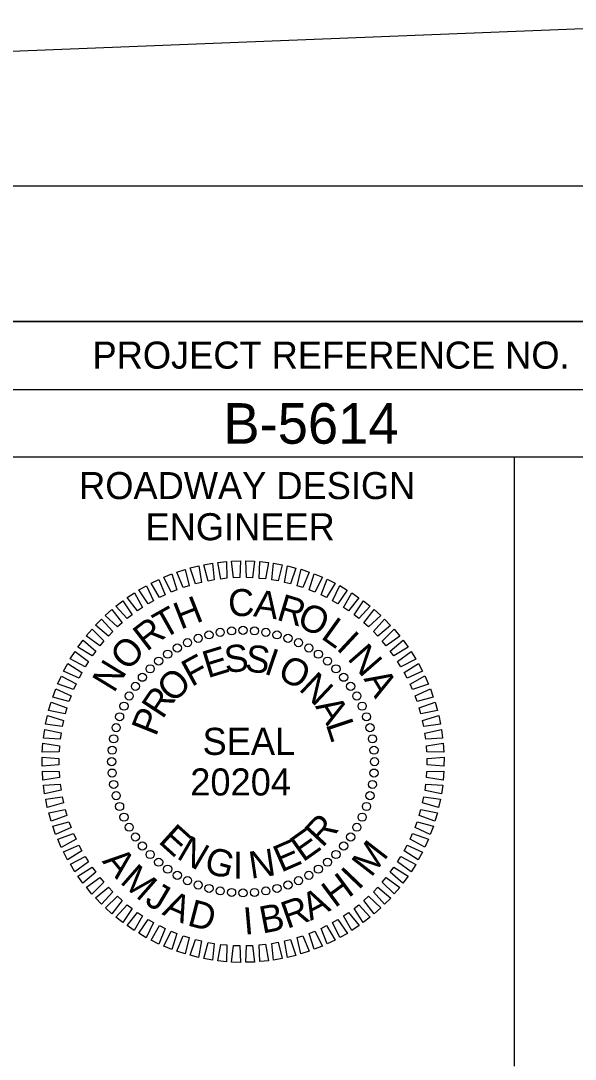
# Model space of a CAD drawing. Extents: x 1637092 to 1638792, y 884647 to 885778.
# Drawn here: x 1638575.6 to 1638677.9, y 885585.9 to 885777.7 of the extents above; entities that cross this region are included whole.
import ezdxf

# ---------------------------------------------------------------- set-up
doc = ezdxf.new("R2010")
doc.units = 0
for name, color, linetype in [('Scratch_Level_3', 7, 'Continuous'), ('Sheet Cutting Line CELL', 7, 'Continuous'), ('Sheet Data Field CELL', 7, 'Continuous'), ('Sheet PE Seal Cell', 7, 'Continuous'), ('Sheet Plan And Profile CELL', 7, 'Continuous'), ('Sheet Profile CELL', 7, 'Continuous'), ('Stewart Plot Border Xerox6279 and LJ5000', 7, 'Continuous')]:
    doc.layers.add(name, color=color, linetype=linetype)

msp = doc.modelspace()

# ---------------------------------------------------------------- linework, layer by layer
at = {"layer": 'Scratch_Level_3'}
msp.add_lwpolyline([(1637316.66, 885722.14), (1637316.66, 884697.14), (1638716.66, 884697.14), (1638716.66, 885777.71)], close=True, dxfattribs=at)
at = {"layer": 'Sheet Cutting Line CELL'}
msp.add_line((1638783.66, 885747.14), (1637099.66, 885747.14), dxfattribs=at)
at = {"layer": 'Sheet PE Seal Cell'}
msp.add_line((1638616.59, 885640.84), (1638616.59, 885640.84), dxfattribs=at)
for points in [[(1638607.82, 885673.68), (1638606.84, 885676.64), (1638608.41, 885677), (1638608.92, 885673.96)], [(1638610.13, 885674.21), (1638609.36, 885677.23), (1638610.95, 885677.49), (1638611.25, 885674.42)], [(1638612.47, 885674.58), (1638611.91, 885677.65), (1638613.52, 885677.79), (1638613.61, 885674.71)], [(1638614.84, 885674.79), (1638614.49, 885677.89), (1638616.11, 885677.91), (1638615.98, 885674.83)], [(1638617.21, 885674.83), (1638617.08, 885677.94), (1638618.7, 885677.86), (1638618.35, 885674.79)], [(1638619.58, 885674.7), (1638619.67, 885677.82), (1638621.27, 885677.62), (1638620.72, 885674.59)], [(1638621.93, 885674.41), (1638622.24, 885677.51), (1638623.83, 885677.21), (1638623.06, 885674.22)], [(1638624.26, 885673.95), (1638624.79, 885677.03), (1638626.35, 885676.61), (1638625.37, 885673.69)], [(1638603.33, 885672.14), (1638601.95, 885674.93), (1638603.46, 885675.51), (1638604.39, 885672.57)], [(1638605.55, 885672.99), (1638604.36, 885675.87), (1638605.91, 885676.34), (1638606.63, 885673.35)], [(1638626.55, 885673.34), (1638627.29, 885676.37), (1638628.82, 885675.84), (1638627.64, 885672.99)], [(1638628.8, 885672.57), (1638629.74, 885675.54), (1638631.23, 885674.91), (1638629.86, 885672.14)], [(1638599.11, 885669.99), (1638597.35, 885672.56), (1638598.76, 885673.35), (1638600.09, 885670.57)], [(1638601.18, 885671.14), (1638599.61, 885673.83), (1638601.07, 885674.51), (1638602.21, 885671.64)], [(1638630.98, 885671.64), (1638632.13, 885674.54), (1638633.57, 885673.8), (1638632.01, 885671.14)], [(1638633.09, 885670.56), (1638634.44, 885673.37), (1638635.83, 885672.54), (1638634.09, 885669.99)], [(1638597.12, 885668.7), (1638595.18, 885671.14), (1638596.54, 885672.02), (1638598.06, 885669.34)], [(1638635.13, 885669.33), (1638636.67, 885672.05), (1638637.99, 885671.12), (1638636.08, 885668.7)], [(1638593.43, 885665.72), (1638591.17, 885667.87), (1638592.39, 885668.93), (1638594.27, 885666.49)], [(1638595.22, 885667.27), (1638593.12, 885669.58), (1638594.41, 885670.55), (1638596.12, 885667.98)], [(1638637.07, 885667.97), (1638638.8, 885670.57), (1638640.05, 885669.55), (1638637.97, 885667.28)], [(1638638.91, 885666.48), (1638640.82, 885668.95), (1638642, 885667.85), (1638639.76, 885665.72)], [(1638591.75, 885664.04), (1638589.35, 885666.03), (1638590.49, 885667.17), (1638592.54, 885664.87)], [(1638640.64, 885664.86), (1638642.72, 885667.19), (1638643.82, 885666.01), (1638641.44, 885664.04)], [(1638590.19, 885662.25), (1638587.66, 885664.07), (1638588.72, 885665.29), (1638590.92, 885663.13)], [(1638642.26, 885663.12), (1638644.49, 885665.3), (1638645.51, 885664.05), (1638643, 885662.25)], [(1638588.76, 885660.36), (1638586.11, 885661.99), (1638587.08, 885663.28), (1638589.43, 885661.28)], [(1638643.75, 885661.28), (1638646.13, 885663.3), (1638647.06, 885661.97), (1638644.43, 885660.36)], [(1638587.47, 885658.37), (1638584.71, 885659.82), (1638585.59, 885661.17), (1638588.07, 885659.34)], [(1638645.11, 885659.33), (1638647.63, 885661.18), (1638648.46, 885659.8), (1638645.72, 885658.37)], [(1638586.32, 885656.29), (1638583.46, 885657.54), (1638584.24, 885658.96), (1638586.85, 885657.3)], [(1638646.33, 885657.3), (1638648.97, 885658.97), (1638649.7, 885657.53), (1638646.88, 885656.29)], [(1638585.31, 885654.14), (1638582.37, 885655.19), (1638583.06, 885656.66), (1638585.77, 885655.19)], [(1638647.41, 885655.18), (1638650.16, 885656.67), (1638650.79, 885655.18), (1638647.88, 885654.14)], [(1638584.46, 885651.93), (1638581.46, 885652.77), (1638582.04, 885654.28), (1638584.85, 885653)], [(1638648.33, 885653), (1638651.18, 885654.29), (1638651.7, 885652.76), (1638648.73, 885651.93)], [(1638583.77, 885649.66), (1638580.71, 885650.29), (1638581.18, 885651.84), (1638584.07, 885650.76)], [(1638649.11, 885650.76), (1638652.03, 885651.84), (1638652.45, 885650.28), (1638649.43, 885649.66)], [(1638583.23, 885647.35), (1638580.14, 885647.76), (1638580.5, 885649.34), (1638583.46, 885648.47)], [(1638649.72, 885648.46), (1638652.71, 885649.34), (1638653.02, 885647.76), (1638649.96, 885647.35)], [(1638582.86, 885645.01), (1638579.74, 885645.2), (1638580, 885646.8), (1638583.01, 885646.14)], [(1638650.17, 885646.13), (1638653.22, 885646.8), (1638653.41, 885645.2), (1638650.34, 885645)], [(1638582.65, 885642.64), (1638579.53, 885642.62), (1638579.67, 885644.23), (1638582.72, 885643.78)], [(1638650.46, 885643.78), (1638653.54, 885644.23), (1638653.63, 885642.62), (1638650.54, 885642.64)], [(1638582.61, 885640.27), (1638579.5, 885640.03), (1638579.52, 885641.65), (1638582.6, 885641.41)], [(1638650.58, 885641.41), (1638653.69, 885641.65), (1638653.66, 885640.03), (1638650.59, 885640.27)], [(1638582.73, 885637.9), (1638579.64, 885637.45), (1638579.56, 885639.06), (1638582.64, 885639.04)], [(1638650.54, 885639.04), (1638653.66, 885639.06), (1638653.52, 885637.45), (1638650.46, 885637.9)], [(1638583.02, 885635.55), (1638579.97, 885634.88), (1638579.77, 885636.48), (1638582.85, 885636.68)], [(1638650.33, 885636.67), (1638653.44, 885636.48), (1638653.19, 885634.88), (1638650.18, 885635.54)], [(1638583.47, 885633.22), (1638580.47, 885632.34), (1638580.17, 885633.92), (1638583.22, 885634.33)], [(1638649.96, 885634.33), (1638653.05, 885633.92), (1638652.68, 885632.34), (1638649.72, 885633.21)], [(1638584.08, 885630.92), (1638581.16, 885629.84), (1638580.74, 885631.4), (1638583.76, 885632.02)], [(1638649.42, 885632.02), (1638652.48, 885631.39), (1638652, 885629.85), (1638649.11, 885630.92)], [(1638584.85, 885628.68), (1638582.01, 885627.39), (1638581.48, 885628.92), (1638584.45, 885629.75)], [(1638648.72, 885629.75), (1638651.73, 885628.91), (1638651.15, 885627.4), (1638648.34, 885628.68)], [(1638585.78, 885626.5), (1638583.03, 885625.01), (1638582.4, 885626.5), (1638585.31, 885627.54)], [(1638647.87, 885627.54), (1638650.81, 885626.49), (1638650.13, 885625.02), (1638647.41, 885626.49)], [(1638586.85, 885624.38), (1638584.22, 885622.71), (1638583.48, 885624.15), (1638586.31, 885625.39)], [(1638646.87, 885625.39), (1638649.73, 885624.14), (1638648.94, 885622.72), (1638646.34, 885624.38)], [(1638588.07, 885622.35), (1638585.56, 885620.5), (1638584.73, 885621.88), (1638587.46, 885623.31)], [(1638645.72, 885623.31), (1638648.48, 885621.87), (1638647.6, 885620.51), (1638645.12, 885622.34)], [(1638589.43, 885620.4), (1638587.05, 885618.38), (1638586.13, 885619.71), (1638588.76, 885621.32)], [(1638644.42, 885621.33), (1638647.08, 885619.69), (1638646.11, 885618.4), (1638643.76, 885620.4)], [(1638590.92, 885618.56), (1638588.69, 885616.38), (1638587.68, 885617.63), (1638590.18, 885619.43)], [(1638642.99, 885619.43), (1638645.53, 885617.61), (1638644.47, 885616.39), (1638642.27, 885618.55)], [(1638592.54, 885616.82), (1638590.47, 885614.49), (1638589.37, 885615.67), (1638591.74, 885617.64)], [(1638641.44, 885617.64), (1638643.84, 885615.65), (1638642.7, 885614.51), (1638640.65, 885616.81)], [(1638594.28, 885615.2), (1638592.37, 885612.73), (1638591.19, 885613.83), (1638593.42, 885615.96)], [(1638639.76, 885615.97), (1638642.02, 885613.81), (1638640.8, 885612.75), (1638638.91, 885615.2)], [(1638596.12, 885613.71), (1638594.39, 885611.11), (1638593.13, 885612.13), (1638595.21, 885614.41)], [(1638637.97, 885614.41), (1638640.07, 885612.1), (1638638.78, 885611.13), (1638637.07, 885613.7)], [(1638598.06, 885612.35), (1638596.52, 885609.63), (1638595.19, 885610.56), (1638597.11, 885612.98)], [(1638600.09, 885611.12), (1638598.74, 885608.31), (1638597.36, 885609.14), (1638599.1, 885611.69)], [(1638634.08, 885611.69), (1638635.84, 885609.12), (1638634.43, 885608.33), (1638633.09, 885611.12)], [(1638636.07, 885612.98), (1638638.01, 885610.54), (1638636.65, 885609.66), (1638635.13, 885612.34)], [(1638602.21, 885610.04), (1638601.06, 885607.14), (1638599.62, 885607.88), (1638601.18, 885610.54)], [(1638604.39, 885609.12), (1638603.44, 885606.14), (1638601.96, 885606.77), (1638603.33, 885609.54)], [(1638629.85, 885609.54), (1638631.24, 885606.75), (1638629.73, 885606.17), (1638628.8, 885609.11)], [(1638632, 885610.54), (1638633.58, 885607.85), (1638632.12, 885607.17), (1638630.98, 885610.04)], [(1638606.63, 885608.34), (1638605.9, 885605.31), (1638604.37, 885605.84), (1638605.54, 885608.69)], [(1638608.92, 885607.73), (1638608.4, 885604.65), (1638606.84, 885605.07), (1638607.81, 885608)], [(1638625.37, 885608), (1638626.35, 885605.04), (1638624.78, 885604.68), (1638624.26, 885607.72)], [(1638627.64, 885608.69), (1638628.82, 885605.81), (1638627.28, 885605.34), (1638626.55, 885608.33)], [(1638611.25, 885607.27), (1638610.95, 885604.17), (1638609.36, 885604.48), (1638610.13, 885607.46)], [(1638613.61, 885606.98), (1638613.52, 885603.86), (1638611.91, 885604.06), (1638612.47, 885607.09)], [(1638615.98, 885606.86), (1638616.1, 885603.74), (1638614.49, 885603.82), (1638614.83, 885606.89)], [(1638618.35, 885606.9), (1638618.69, 885603.79), (1638617.08, 885603.77), (1638617.21, 885606.85)], [(1638620.71, 885607.1), (1638621.27, 885604.03), (1638619.66, 885603.89), (1638619.58, 885606.97)], [(1638623.06, 885607.47), (1638623.83, 885604.45), (1638622.23, 885604.19), (1638621.93, 885607.26)]]:
    msp.add_lwpolyline(points, close=True, dxfattribs=at)
for centre in [(1638612.38, 885664.72), (1638614.48, 885665), (1638616.59, 885665.09), (1638618.71, 885665), (1638620.8, 885664.72), (1638606.34, 885662.82), (1638608.3, 885663.63), (1638610.32, 885664.26), (1638622.87, 885664.26), (1638624.89, 885663.63), (1638626.84, 885662.82), (1638602.68, 885660.7), (1638604.47, 885661.84), (1638628.72, 885661.84), (1638630.5, 885660.7), (1638601.01, 885659.42), (1638632.18, 885659.42), (1638599.45, 885657.99), (1638633.74, 885657.99), (1638596.73, 885654.75), (1638598.02, 885656.43), (1638635.17, 885656.43), (1638636.46, 885654.75), (1638595.59, 885652.97), (1638637.59, 885652.97), (1638594.62, 885651.09), (1638638.57, 885651.09), (1638593.81, 885649.13), (1638639.38, 885649.13), (1638593.17, 885647.12), (1638640.02, 885647.12), (1638592.71, 885645.05), (1638640.47, 885645.05), (1638592.44, 885642.95), (1638640.75, 885642.95), (1638592.34, 885640.84), (1638640.84, 885640.84), (1638592.44, 885638.73), (1638640.75, 885638.73), (1638592.71, 885636.63), (1638640.47, 885636.63), (1638593.17, 885634.56), (1638640.02, 885634.56), (1638593.81, 885632.55), (1638639.38, 885632.55), (1638594.62, 885630.59), (1638638.57, 885630.59), (1638595.59, 885628.72), (1638637.59, 885628.72), (1638596.73, 885626.93), (1638636.46, 885626.93), (1638598.02, 885625.25), (1638635.17, 885625.25), (1638599.45, 885623.69), (1638601.01, 885622.26), (1638632.18, 885622.26), (1638633.74, 885623.69), (1638602.68, 885620.98), (1638630.5, 885620.98), (1638604.47, 885619.84), (1638606.34, 885618.86), (1638626.84, 885618.86), (1638628.72, 885619.84), (1638608.3, 885618.05), (1638610.32, 885617.42), (1638612.38, 885616.96), (1638614.48, 885616.68), (1638616.59, 885616.59), (1638618.71, 885616.68), (1638620.8, 885616.96), (1638622.87, 885617.42), (1638624.89, 885618.05)]:
    msp.add_circle(centre, 0.75, dxfattribs=at)
at = {"layer": 'Sheet Plan And Profile CELL'}
for p, q in [((1638566.61, 885709.59), (1638766.66, 885709.59)), ((1638666.63, 885697.09), (1638666.63, 885584.59))]:
    msp.add_line(p, q, dxfattribs=at)
for points in [[(1638766.66, 885722.14), (1637266.66, 885722.14), (1637266.66, 884672.14), (1638766.66, 884672.14)], [(1638566.61, 885722.14), (1638766.66, 885722.14), (1638766.66, 885697.09), (1638566.61, 885697.09)]]:
    msp.add_lwpolyline(points, close=True, dxfattribs=at)
at = {"layer": 'Sheet Profile CELL'}
msp.add_line((1638566.61, 885709.59), (1638766.66, 885709.59), dxfattribs=at)
for points in [[(1638766.66, 885722.14), (1637266.66, 885722.14), (1637266.66, 884672.14), (1638766.66, 884672.14)], [(1638566.61, 885722.14), (1638766.66, 885722.14), (1638766.66, 885697.09), (1638566.61, 885697.09)]]:
    msp.add_lwpolyline(points, close=True, dxfattribs=at)
at = {"layer": 'Stewart Plot Border Xerox6279 and LJ5000'}
msp.add_lwpolyline([(1637091.66, 884647.14), (1638791.66, 884647.14), (1638791.66, 885747.14), (1637091.66, 885747.14)], close=True, dxfattribs=at)

# ---------------------------------------------------------------- texts
at = {"layer": 'Sheet Data Field CELL'}
msp.add_text('B-5614', height=7.5, rotation=360, dxfattribs=at).set_placement((1638612.96, 885699.57))
at = {"layer": 'Sheet PE Seal Cell'}
for s, rotation, p in [('C', 1.9618, (1638613.92, 885667.64)), ('H', 21.601, (1638605.07, 885665.18)), ('A', 352.4568, (1638618.39, 885667.71)), ('R', 343.4093, (1638622.59, 885667.1)), ('T', 29.3903, (1638601.88, 885663.4)), ('O', 335.2006, (1638626.28, 885665.97)), ('R', 37.5989, (1638598.81, 885661.07)), ('L', 324.4755, (1638630.78, 885663.73)), ('O', 48.3241, (1638595.36, 885657.4)), ('I', 317.0103, (1638633.64, 885661.69)), ('E', 16.986, (1638610.06, 885656.23)), ('S', 5.2237, (1638613.34, 885657.24)), ('S', 353.2648, (1638616.81, 885657.56)), ('I', 341.3058, (1638620.26, 885657.15)), ('N', 311.0704, (1638635.7, 885659.82)), ('N', 58.5345, (1638592.76, 885653.38)), ('F', 28.6639, (1638607.08, 885654.59)), ('O', 332.5504, (1638622.7, 885656.4)), ('O', 44.4727, (1638603.7, 885651.48)), ('N', 316.7416, (1638626.71, 885654.15)), ('A', 300.8599, (1638638.77, 885656.13)), ('R', 56.5721, (1638601.75, 885648.54)), ('A', 301.6915, (1638629.82, 885651.06)), ('P', 68.3344, (1638600.5, 885645.35)), ('L', 288.3556, (1638631.82, 885647.74)), ('SEAL', 360, (1638609.12, 885642.09)), ('20204', 360, (1638606.85, 885634.59)), ('R', 47.043, (1638631.23, 885624.82)), ('E', 317.8506, (1638600.78, 885625.98)), ('N', 329.6129, (1638604.14, 885623.07)), ('E', 35.2807, (1638627.65, 885622.18)), ('G', 344.6629, (1638609.19, 885620.45)), ('E', 23.5185, (1638623.62, 885620.31)), ('M', 52.1895, (1638640.23, 885619.31)), ('A', 309.7469, (1638590.48, 885622.39)), ('I', 359.713, (1638614.73, 885619.22)), ('N', 8.4684, (1638618.05, 885619.19)), ('M', 318.7944, (1638593.7, 885618.52)), ('I', 46.2495, (1638637.88, 885616.98)), ('H', 36.4966, (1638633.53, 885613.72)), ('J', 329.5005, (1638598.25, 885614.65)), ('A', 336.3384, (1638601.5, 885612.66)), ('D', 345.3859, (1638606.12, 885610.63)), ('R', 19.2405, (1638624.72, 885609.92)), ('A', 27.4491, (1638629.05, 885611.39)), ('I', 4.9584, (1638616.84, 885608.87)), ('B', 10.8984, (1638620.15, 885609.06))]:
    msp.add_text(s, height=5, rotation=rotation, dxfattribs=at).set_placement(p)
at = {"layer": 'Sheet Plan And Profile CELL'}
msp.add_text('PROJECT REFERENCE NO.', height=5.0001, rotation=360, dxfattribs=at).set_placement((1638588.81, 885713.44))
at = {"layer": 'Sheet Profile CELL'}
for s, height, p in [('PROJECT REFERENCE NO.', 5.0001, (1638588.82, 885713.45)), ('ROADWAY DESIGN', 5.0001, (1638586.34, 885689.34)), ('ENGINEER', 5, (1638598.59, 885681.74))]:
    msp.add_text(s, height=height, dxfattribs=at).set_placement(p)

doc.saveas('drawing.dxf')
